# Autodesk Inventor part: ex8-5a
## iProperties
Author: Administrator
Created: 2001-10
Part Number: ex8-5a
Document SubType Name: Modeling
Designer: Administrator
Control State: 0
Master: False
Checked Out: False
PropertySet Name: Design Tracking Control
Shininess: 64.0
Angle Display Precision: 2
Document Length Units: 11272
Document Angle Units: 11286
Document Time Units: 11279
Document Mass Units: 11290
Document Length Units Precision: 3
Document Angle Units Precision: 2
Compacted: False
PropertySet Name: _Private Model Information
Density: 0.0
Volumn: 0.0
Area: 0.0
PropertySet Name: Model Information
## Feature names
1. Extrusion1
